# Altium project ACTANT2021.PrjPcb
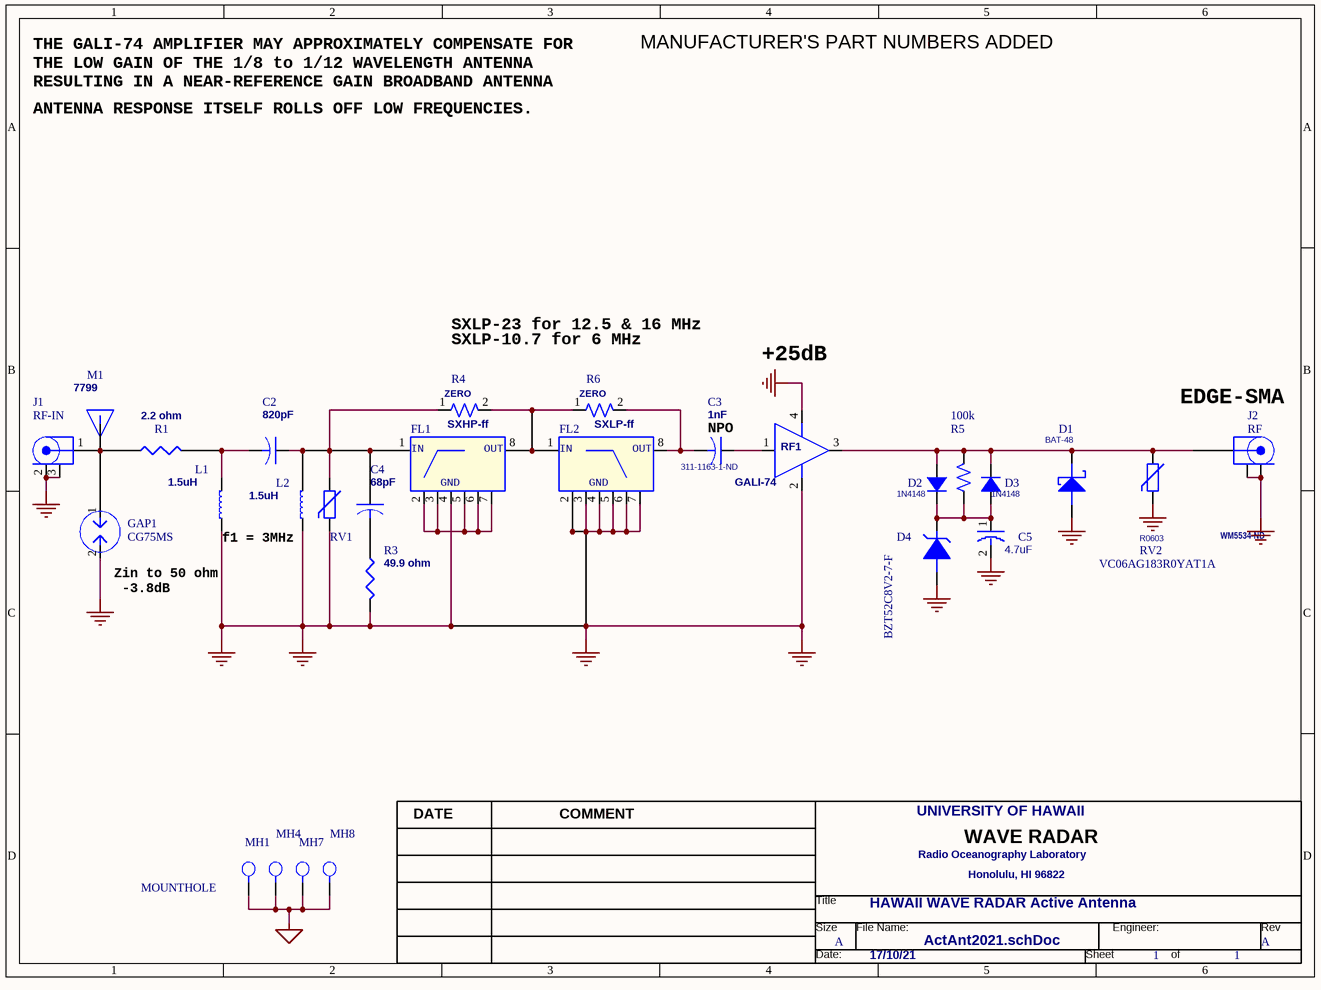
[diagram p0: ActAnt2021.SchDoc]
1 sheet, 30 parts. Net scope: global (net labels, ports and power ports of the same name join across sheets).
Board file: ACTANT2021.PcbDoc

## Sheet ActAnt2021.SchDoc
size 246 x 182 mm; Date: 17/10/21; SheetNumber: 1; SheetTotal: 1

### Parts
(Parts that share a designator on the sheet are numbered #1, #2 ... from top to bottom, then left to right.)
*#1  DCB  (value not drawn)  (graphical)
*#2  Page Count: 1  Page Size: A  OrgAddr3: Honolulu, HI 96822  OrgAddr1: Radio Oceanography Laboratory  OrgName: UNIVERSITY OF HAWAII  Title: HAWAII WAVE RADAR Active Antenna  Doc: ActAnt2021.schDoc  Page Modify Date: 17/10/21  (hidden comment: HWRadar)  (graphical)
C2  820pF  [C1206]
C3  1nF  DK Stock: 311-1163-1-ND  [C1206]
C4  68pF  [C1206]
C5  4.7uF  [C1206]
D1  BAT-48  [SOD123]
D2  1N4148  [SOD123]
D3  1N4148  [SOD123]
D4  BZT52C8V2-7-F  [SOD123]
FL1  SXHP-ff  [HF1149]
FL2  SXLP-ff  [HF1149]
GAP1  CG75MS  [SG-1]
J1  RF-IN  [SMA]
J2  RF  DK Stock: WM5534-ND  [SMA]
L1  1.5uH  [L1812]
L2  1.5uH  [L1812]
M1  7799  [7799]
MH1  MOUNTHOLE  [MOUNTHOLE]
MH4  MOUNTHOLE  [MOUNTHOLE]  (value not drawn)
MH7  MOUNTHOLE  [MOUNTHOLE]  (value not drawn)
MH8  MOUNTHOLE  [MOUNTHOLE]  (value not drawn)
R1  2.2 ohm  [R1206]
R3  49.9 ohm  [R1206]
R4  ZERO  [R1206]
R5  100k  [R1206]
R6  ZERO  [R1206]
RF1  GALI-74  [GVA-84]
RV1  VC06AG183R0YAT1A  [R0603]  (value not drawn)
RV2  VC06AG183R0YAT1A  [R0603]

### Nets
GND: C5.2 D1.ANODE D4.ANODE FL1.4(GND) FL2.2(GND) FL2.3(GND) FL2.4(GND) FL2.5(GND) FL2.6(GND) FL2.7(GND) GAP1.2 J1.2(SHIELD) J1.3(SHIELD) J2.2(SHIELD) J2.3(SHIELD) L1.2 L2.2 MH1.1(PAD) MH4.1(PAD) MH7.1(PAD) MH8.1(PAD) R3.2 RF1.2(GND) RF1.4(GND) RV1.2 RV2.2
NetC2_1: C2.1 C4.1 FL1.1(IN) L2.1 R4.1 RV1.1
NetC2_2: C2.2 L1.1 R1.2
NetC3_1: C3.1 RF1.1(IN)
NetC3_2: C3.2 FL2.8(OUT) R6.2
NetC4_2: C4.2 R3.1
NetC5_1: C5.1 D2.CATH D3.ANOD D4.CATHODE R5.1
NetD1_CATHODE: D1.CATHODE D2.ANOD D3.CATH J2.1(CENTER) R5.2 RF1.3(OUT) RV2.1
NetFL1_2: FL1.2(GND) FL1.3(GND) FL1.5(GND) FL1.6(GND) FL1.7(GND)
NetFL1_8: FL1.8(OUT) FL2.1(IN) R4.2 R6.1
NetGAP1_1: GAP1.1 J1.1(CENTER) M1.1(TP) M1.2 M1.3 M1.4 M1.5 M1.6 R1.1

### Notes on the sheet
- MANUFACTURER'S PART NUMBERS ADDED
- THE GALI-74 AMPLIFIER MAY APPROXIMATELY COMPENSATE FOR
  THE LOW GAIN OF THE 1/8 to 1/12 WAVELENGTH ANTENNA
- RESULTING IN A NEAR-REFERENCE GAIN BROADBAND ANTENNA
- ANTENNA RESPONSE ITSELF ROLLS OFF LOW FREQUENCIES.
- SXLP-23 for 12.5 & 16 MHz
- SXLP-10.7 for 6 MHz
- +25dB
- (near C3) NPO
- EDGE-SMA
- (near GAP1) Zin to 50 ohm
  -3.8dB
- (near L1) f1 = 3MHz

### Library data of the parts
*#2 = HWRadar: OrgAddr2: 2525 Correa Road; Engineer:: <ENG>
C2 = CAP: MFR: Kemet; MFR PART: C1206C821J5GACTU; DK Stock: 399-8212-1-ND
C3 = CAP: MFR: Yageo; MFR PART: CC1206JRNPO9BN102
C4 = CAP: MFR: Yageo; MFR PART: CC1206JRNPO9BN680; DK Stock: 311-1160-1-ND
C5 = C1206: MFR: Samsung; MFR PART: CL32B475KBUYNNE; DK Stock: 1276-1292-1-ND; PCB Footprint: C1210
D1 = DIODE SCHOTTKY: MFR: STMicroelectronic; MFR PART: BAT48ZFILM; DK Stock: 497-5712-1-ND
D2 D3 = DIODE2: MFR: Diodes Inc.; MFR PART: 1N4148W-7-F; DK Stock: 1N4148W-FDICT-ND
D4 = ZENER: MFR: Diodes Inc.; DK Stock: BZT52C8V2-FDICT-ND
FL1 = LP FILTER_2: MFR PART: SXHP-xx+; MFR: MiniCircuits; PCB Footprint: FILTX2
FL2 = LP FILTER_1: MFR PART: SXLP-xx+; PCB Footprint: FILTX2; DK Stock: MiniCircuits
GAP1 = SPARK GAP: MFR: Littelfuse Inc.; DK Stock: F2723CT-ND
J1 = SMA-4G_0: MFR: MOLEX; MFR PART: 0732511150; PCB Footprint: SMA_J610EDGE; DK Stock: WM5534-ND
J2 = SMA-4G_0: MFR: MOLEX; MFR PART: 0732511150; PCB Footprint: SMA_J610EDGE
L1 L2 = IND: MFR: TDK Corporation; MFR PART: NLFC453232T-1R5M-PF; DK Stock: 445-6465-2-ND
M1 = 7799: Borne à vis à 6 broches, robinet d’alimentation M4 à travers le trou; MFR: Keystone electronics
R1 = RESISTOR_Dup1: MFR: Yageo; MFR PART: RC1206FR-072R2L; DK Stock: 311-2.20FRCT-ND
R3 = RESISTOR_Dup1: MFR: Yageo; MFR PART: RC1206FR-0749R9L; DK Stock: 311-49.9FRCT-ND
R4 = R1206: MFR: Yageo; MFR PART: RC1206JR-070RL; DK Stock: 311-0.0ERCT-ND; PCB Footprint: ZEROHM
R5 = RES1206: MFR: Yageo; MFR PART: RC1206FR-07100KL; DK Stock: 311-100KFRCT-ND
R6 = R1206: MFR: Yageo; MFR PART: RC1206JR-070RL; PCB Footprint: ZEROHM; DK Stock: 311-0.0ERCT-ND
RF1 = GVA-84: MFR PART: GALI-74+; DK Stock: MiniCircuits
RV1 RV2 = VARISTOR: MFR: AVX Corporation; DK Stock: 478-5819-1-ND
